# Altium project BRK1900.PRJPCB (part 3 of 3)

## Sheet DisplayPort-Sink-SATA.SchDoc: BRK1900 - DisplayPort Sink, SATA
size C; Organization: Opal Kelly; Address1: 13500 SW 72nd Ave STE 100; Address3: Portland, OR  97223; Address4: http://www.opalkelly.com; DocumentNumber: xxx; Revision: 1; SheetNumber: 6; SheetTotal: 9; PageSetup: Record=PageOptions¦CenterHorizontal=True¦CenterVertical=True¦PrintScale=0.52¦XCorrection=1.00¦YCorrection=1.00¦PrintKind=0¦BorderSize=5000000¦LeftOffset=0¦BottomOffset=0¦Orientation=2¦PaperLength=1000¦PaperWidth=1000¦Scale=100¦PaperSource=7¦PrintQuality=-4¦MediaType=1¦DitherType=10¦PaperKind=Letter¦PrintScaleMode=1
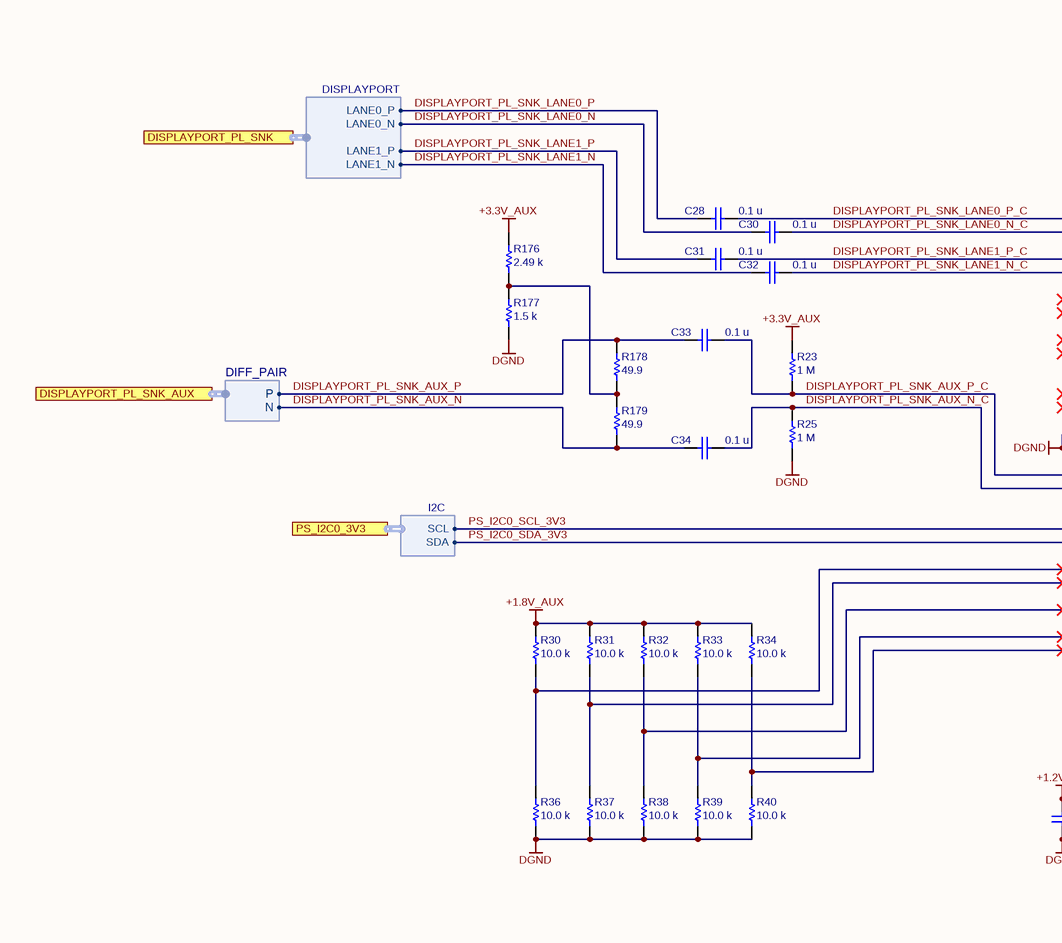
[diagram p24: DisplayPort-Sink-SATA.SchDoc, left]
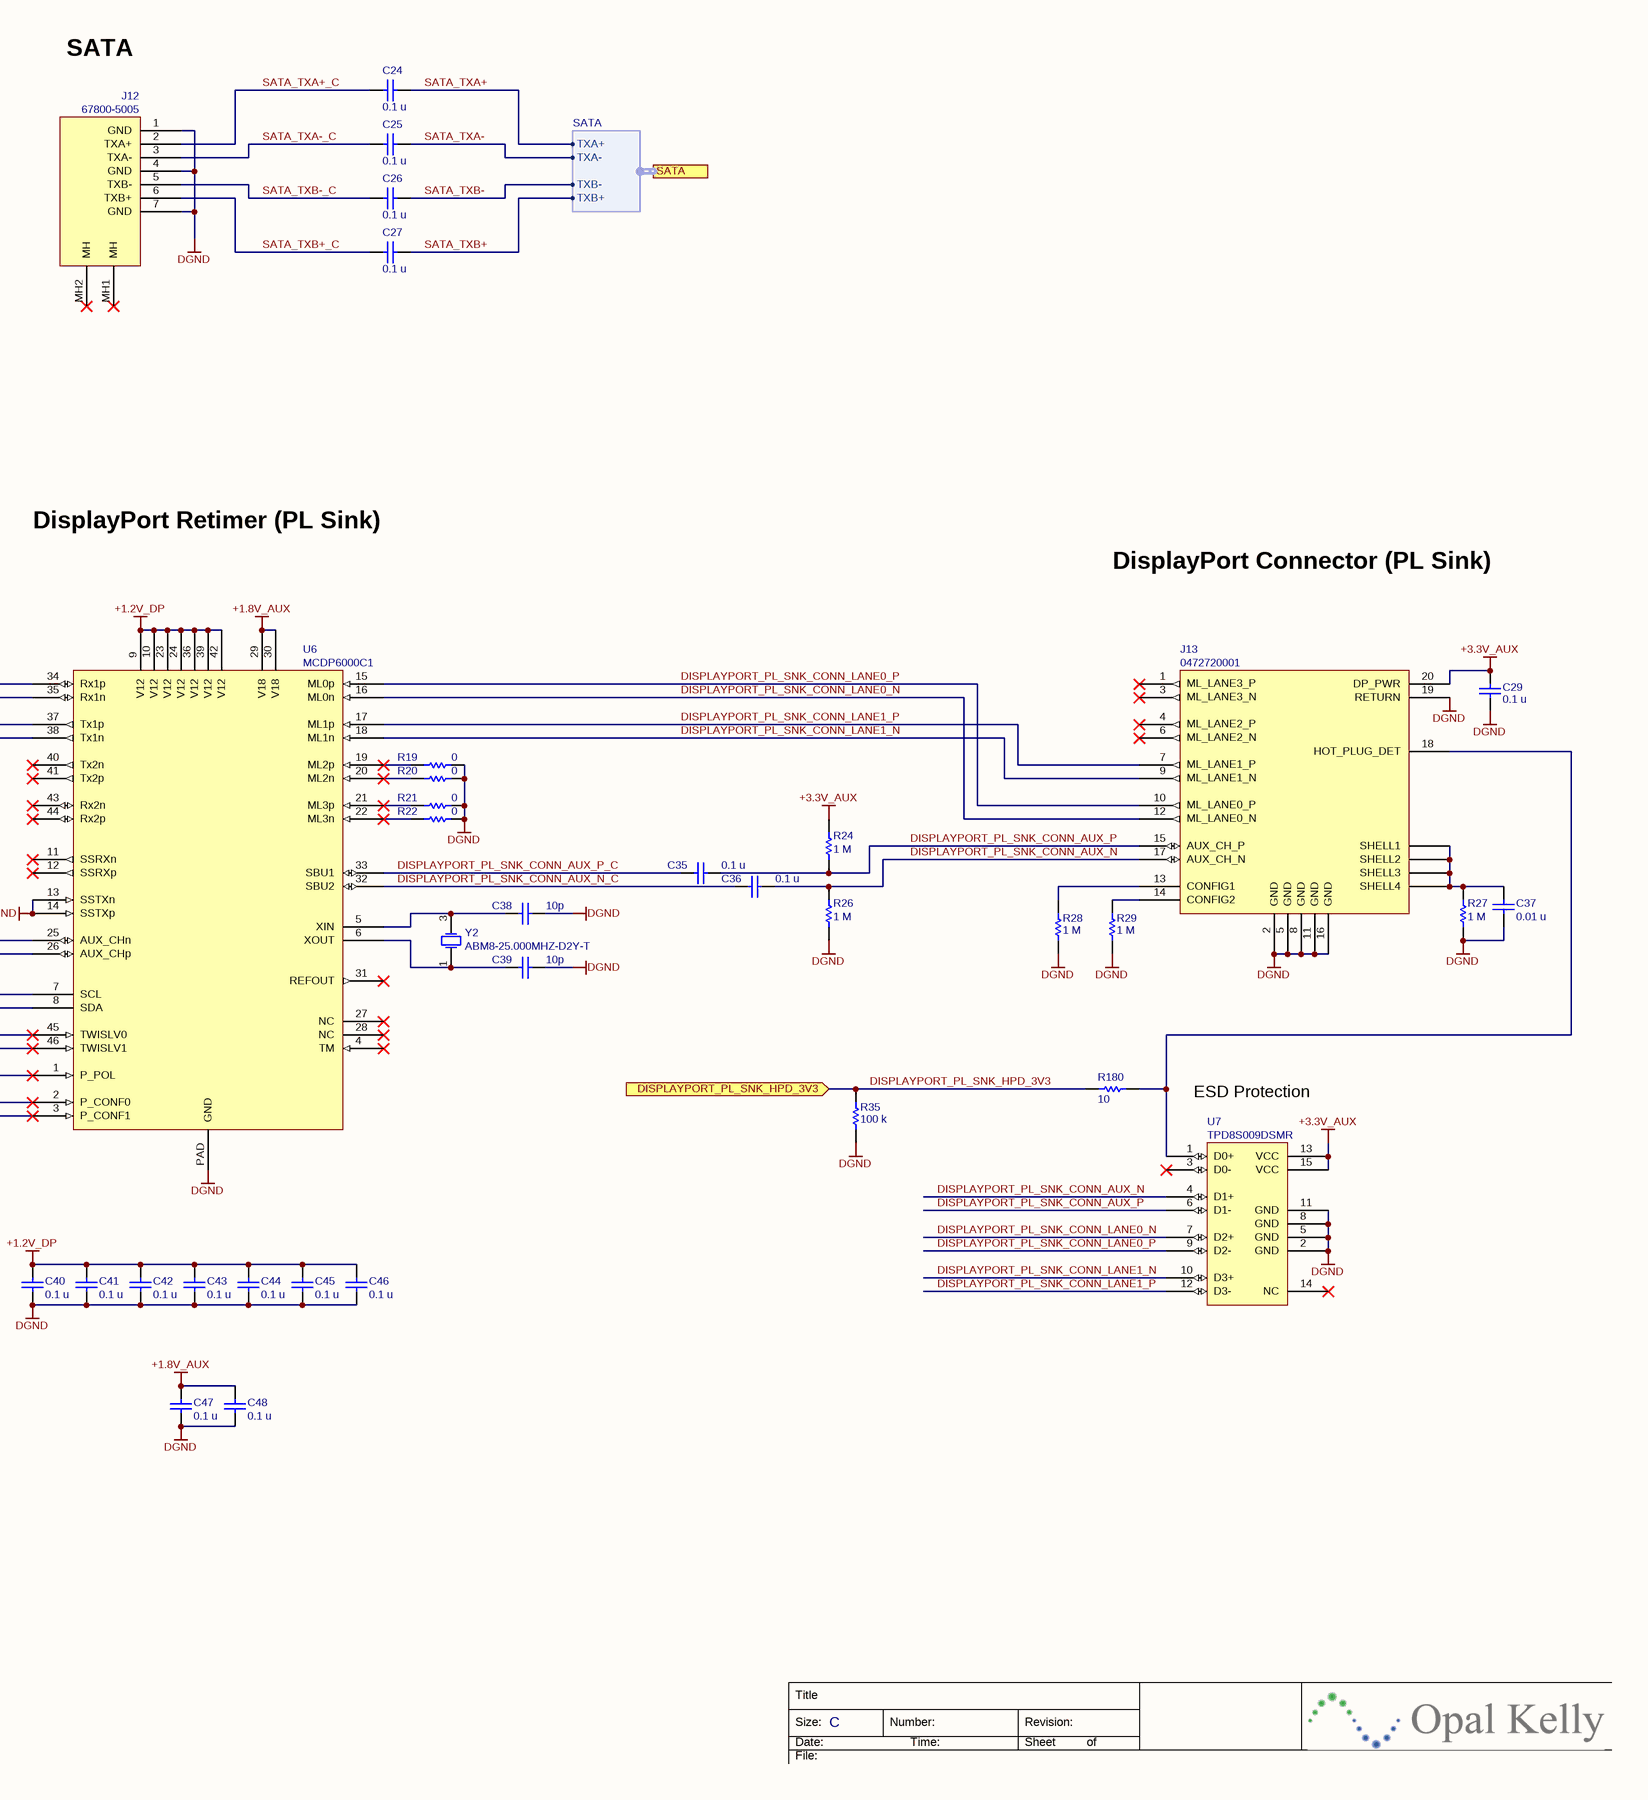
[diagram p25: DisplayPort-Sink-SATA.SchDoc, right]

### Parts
C24  value 0.1 u  [CAPC1005X06A]  (hidden comment: SM-0402, 10%, 10v)
C25  value 0.1 u  [CAPC1005X06A]  (hidden comment: SM-0402, 10%, 10v)
C26  value 0.1 u  [CAPC1005X06A]  (hidden comment: SM-0402, 10%, 10v)
C27  value 0.1 u  [CAPC1005X06A]  (hidden comment: SM-0402, 10%, 10v)
C28  value 0.1 u  [CAPC1005X06A]  (hidden comment: SM-0402, 10%, 10v)
C29  value 0.1 u  [CAPC1005X06A]  (hidden comment: SM-0402, 10%, 10v)
C30  value 0.1 u  [CAPC1005X06A]  (hidden comment: SM-0402, 10%, 10v)
C31  value 0.1 u  [CAPC1005X06A]  (hidden comment: SM-0402, 10%, 10v)
C32  value 0.1 u  [CAPC1005X06A]  (hidden comment: SM-0402, 10%, 10v)
C33  value 0.1 u  [CAPC1005X06A]  (hidden comment: SM-0402, 10%, 10v)
C34  value 0.1 u  [CAPC1005X06A]  (hidden comment: SM-0402, 10%, 10v)
C35  value 0.1 u  [CAPC1005X06A]  (hidden comment: SM-0402, 10%, 10v)
C36  value 0.1 u  [CAPC1005X06A]  (hidden comment: SM-0402, 10%, 10v)
C37  value 0.01 u  [CAPC1005X06A]  (hidden comment: C0402C103K4RACTU)
C38  value 10p  [CAPC1005X06A]  (hidden comment: CBR04C100J5GAC)
C39  value 10p  [CAPC1005X06A]  (hidden comment: CBR04C100J5GAC)
C40  value 0.1 u  [CAPC1005X06A]  (hidden comment: C0402C104K8PACTU)
C41  value 0.1 u  [CAPC1005X06A]  (hidden comment: C0402C104K8PACTU)
C42  value 0.1 u  [CAPC1005X06A]  (hidden comment: C0402C104K8PACTU)
C43  value 0.1 u  [CAPC1005X06A]  (hidden comment: C0402C104K8PACTU)
C44  value 0.1 u  [CAPC1005X06A]  (hidden comment: C0402C104K8PACTU)
C45  value 0.1 u  [CAPC1005X06A]  (hidden comment: C0402C104K8PACTU)
C46  value 0.1 u  [CAPC1005X06A]  (hidden comment: C0402C104K8PACTU)
C47  value 0.1 u  [CAPC1005X06A]  (hidden comment: C0402C104K8PACTU)
C48  value 0.1 u  [CAPC1005X06A]  (hidden comment: C0402C104K8PACTU)
J12  67800-5005  [MOLEX-67800-5005]
J13  0472720001  [0472720001]
R19  value 0  [RESC1005X06A]  (hidden comment: CRCW04020000Z0ED)
R20  value 0  [RESC1005X06A]  (hidden comment: CRCW04020000Z0ED)
R21  value 0  [RESC1005X06A]  (hidden comment: CRCW04020000Z0ED)
R22  value 0  [RESC1005X06A]  (hidden comment: CRCW04020000Z0ED)
R23  value 1 M  [RESC1005X06A]  (hidden comment: CRCW04021M00FKEDC)
R24  value 1 M  [RESC1005X06A]  (hidden comment: CRCW04021M00FKEDC)
R25  value 1 M  [RESC1005X06A]  (hidden comment: CRCW04021M00FKEDC)
R26  value 1 M  [RESC1005X06A]  (hidden comment: CRCW04021M00FKEDC)
R27  value 1 M  [RESC1005X06A]  (hidden comment: CRCW04021M00FKEDC)
R28  value 1 M  [RESC1005X06A]  (hidden comment: CRCW04021M00FKEDC)
R29  value 1 M  [RESC1005X06A]  (hidden comment: CRCW04021M00FKEDC)
R30  value 10.0 k  [RESC1005X06A]  (hidden comment: CRCW040210K0FKED)
R31  value 10.0 k  [RESC1005X06A]  (hidden comment: CRCW040210K0FKED)
R32  value 10.0 k  [RESC1005X06A]  (hidden comment: CRCW040210K0FKED)
R33  value 10.0 k  [RESC1005X06A]  (hidden comment: CRCW040210K0FKED)
R34  value 10.0 k  [RESC1005X06A]  (hidden comment: CRCW040210K0FKED)
R35  value 100 k  [RESC1005X06A]  (hidden comment: CRCW0402100KFKED)
R36  value 10.0 k  [RESC1005X06A]  (hidden comment: CRCW040210K0FKED)
R37  value 10.0 k  [RESC1005X06A]  (hidden comment: CRCW040210K0FKED)
R38  value 10.0 k  [RESC1005X06A]  (hidden comment: CRCW040210K0FKED)
R39  value 10.0 k  [RESC1005X06A]  (hidden comment: CRCW040210K0FKED)
R40  value 10.0 k  [RESC1005X06A]  (hidden comment: CRCW040210K0FKED)
R176  value 2.49 k  [RESC1005X06A]  (hidden comment: CRCW04022K49FKED)
R177  value 1.5 k  [RESC1005X06A]  (hidden comment: CRCW04021K50FKED)
R178  value 49.9  [RESC1005X06A]  (hidden comment: CRCW040249R9FKEDC)
R179  value 49.9  [RESC1005X06A]  (hidden comment: CRCW040249R9FKEDC)
R180  value 10  [RESC1005X06A]  (hidden comment: CRCW040210R0FKED)
U6  MCDP6000C1  [MCDP6000]
U7  TPD8S009DSMR  [TPD8S009DSMR]
Y2  ABM8-25.000MHZ-D2Y-T  [OSC_SMD_32x25]

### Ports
DISPLAYPORT_PL_SNK (harness DISPLAYPORT), DISPLAYPORT_PL_SNK_AUX (harness DIFF_PAIR), DISPLAYPORT_PL_SNK_HPD_3V3 (in), PS_I2C0_3V3 (harness I2C), SATA (harness SATA)

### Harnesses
DISPLAYPORT: LANE0_P, LANE0_N, LANE1_P, LANE1_N
DIFF_PAIR: P, N
SATA: TXA+, TXA-, TXB-, TXB+
I2C: SCL, SDA

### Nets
+1.2V_DP: C40.2 C41.2 C42.2 C43.2 C44.2 C45.2 C46.2 U6.9(V12) U6.10(V12) U6.23(V12) U6.24(V12) U6.36(V12) U6.39(V12) U6.42(V12)
+1.8V_AUX: C47.2 C48.2 R30.2 R31.2 R32.2 R33.2 R34.2 U6.29(V18) U6.30(V18)
+3.3V_AUX: C29.2 J13.20(DP_PWR) R23.2 R24.2 R176.2 U7.13(VCC) U7.15(VCC)
DGND: C29.1 C37.1 C38.2 C39.2 C40.1 C41.1 C42.1 C43.1 C44.1 C45.1 C46.1 C47.1 C48.1 J12.1(GND) J12.4(GND) J12.7(GND) J13.2(GND) J13.5(GND) J13.8(GND) J13.11(GND) J13.16(GND) J13.19(RETURN) R19.2 R20.2 R21.2 R22.2 R25.1 R26.1 R27.1 R28.1 R29.1 R35.1 R36.1 R37.1 R38.1 R39.1 R40.1 R177.1 U6.13(SSTXn) U6.14(SSTXp) U6.PAD(GND) U7.2(GND) U7.5(GND) U7.8(GND) U7.11(GND)
DISPLAYPORT_PL_SNK_AUX_N: C34.2 R179.1 ; port DISPLAYPORT_PL_SNK_AUX.N
DISPLAYPORT_PL_SNK_AUX_N_C: C34.1 R25.2 U6.26(AUX_CHp)
DISPLAYPORT_PL_SNK_AUX_P: C33.2 R178.2 ; port DISPLAYPORT_PL_SNK_AUX.P
DISPLAYPORT_PL_SNK_AUX_P_C: C33.1 R23.1 U6.25(AUX_CHn)
DISPLAYPORT_PL_SNK_CONN_AUX_N: C36.1 J13.17(AUX_CH_N) R26.2 U7.4(D1+)
DISPLAYPORT_PL_SNK_CONN_AUX_N_C: C36.2 U6.32(SBU2)
DISPLAYPORT_PL_SNK_CONN_AUX_P: C35.1 J13.15(AUX_CH_P) R24.1 U7.6(D1-)
DISPLAYPORT_PL_SNK_CONN_AUX_P_C: C35.2 U6.33(SBU1)
DISPLAYPORT_PL_SNK_CONN_LANE0_N: J13.12(ML_LANE3_N) U6.16(ML0n) U7.7(D2+)
DISPLAYPORT_PL_SNK_CONN_LANE0_P: J13.10(ML_LANE3_P) U6.15(ML0p) U7.9(D2-)
DISPLAYPORT_PL_SNK_CONN_LANE1_N: J13.9(ML_LANE2_N) U6.18(ML1n) U7.10(D3+)
DISPLAYPORT_PL_SNK_CONN_LANE1_P: J13.7(ML_LANE2_P) U6.17(ML1p) U7.12(D3-)
DISPLAYPORT_PL_SNK_HPD_3V3: R35.2 R180.1 ; port DISPLAYPORT_PL_SNK_HPD_3V3
DISPLAYPORT_PL_SNK_LANE0_N: C30.2 ; port DISPLAYPORT_PL_SNK.LANE0_N
DISPLAYPORT_PL_SNK_LANE0_N_C: C30.1 U6.35(Rx1n)
DISPLAYPORT_PL_SNK_LANE0_P: C28.2 ; port DISPLAYPORT_PL_SNK.LANE0_P
DISPLAYPORT_PL_SNK_LANE0_P_C: C28.1 U6.34(Rx1p)
DISPLAYPORT_PL_SNK_LANE1_N: C32.2 ; port DISPLAYPORT_PL_SNK.LANE1_N
DISPLAYPORT_PL_SNK_LANE1_N_C: C32.1 U6.38(Tx1n)
DISPLAYPORT_PL_SNK_LANE1_P: C31.2 ; port DISPLAYPORT_PL_SNK.LANE1_P
DISPLAYPORT_PL_SNK_LANE1_P_C: C31.1 U6.37(Tx1p)
PS_I2C0_SCL_3V3: U6.7(SCL) ; port PS_I2C0_3V3.SCL
PS_I2C0_SDA_3V3: U6.8(SDA) ; port PS_I2C0_3V3.SDA
SATA_TXA+: C24.2 ; port SATA.TXA+
SATA_TXA+_C: C24.1 J12.2(TXA+)
SATA_TXA-: C25.2 ; port SATA.TXA-
SATA_TXA-_C: C25.1 J12.3(TXA-)
SATA_TXB+: C27.2 ; port SATA.TXB+
SATA_TXB+_C: C27.1 J12.6(TXB+)
SATA_TXB-: C26.2 ; port SATA.TXB-
SATA_TXB-_C: C26.1 J12.5(TXB-)
NetC37_2: C37.2 J13.SHELL1 J13.SHELL2 J13.SHELL3 J13.SHELL4 R27.2
NetC38_1: C38.1 U6.5(XIN) Y2.3(OSC2)
NetC39_1: C39.1 U6.6(XOUT) Y2.1(OSC1)
NetJ13_13: J13.13(CONFIG1) R28.2
NetJ13_14: J13.14(CONFIG2) R29.2
NetJ13_18: J13.18(HOT_PLUG_DET) R180.2 U7.1(D0+)
NetR19_1: R19.1 U6.19(ML2p)
NetR20_1: R20.1 U6.20(ML2n)
NetR21_1: R21.1 U6.21(ML3p)
NetR22_1: R22.1 U6.22(ML3n)
NetR30_1: R30.1 R36.2 U6.45(TWISLV0)
NetR31_1: R31.1 R37.2 U6.46(TWISLV1)
NetR32_1: R32.1 R38.2 U6.1(P_POL)
NetR33_1: R33.1 R39.2 U6.2(P_CONF0)
NetR34_1: R34.1 R40.2 U6.3(P_CONF1)
NetR176_1: R176.1 R177.2 R178.1 R179.2

Not connected (* = marked no-connect by the designer): J12 MH1(MH)* MH2(MH)*; J13 1(ML_LANE0_P)* 3(ML_LANE0_N)* 4(ML_LANE1_P)* 6(ML_LANE1_N)*; U6 4(TM)* 11(SSRXn)* 12(SSRXp)* 27(NC)* 28(NC)* 31(REFOUT)* 40(Tx2n)* 41(Tx2p)* 43(Rx2n)* 44(Rx2p)*; U7 3(D0-)* 14(NC)*

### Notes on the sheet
- SATA
- DisplayPort Retimer (PL Sink)
- DisplayPort Connector (PL Sink)
- ESD Protection
- Title
- Size:
- Date:
- File:
- C
- Number:
- Time:
- Revision:
- Sheet
- of

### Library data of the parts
C24-C36 = 000070: Partnumber: 000070; manufacturer: Kemet; manufacturer_pn: C0402C104K8PACTU; ValueFloat: 1E-7; id: 750; inventory_price: 0.0023; reorder_quantity: 70000; x_tolerance: 10
C37 = 000295: Partnumber: 000295; manufacturer: Kemet; ValueFloat: 1E-8; x_tolerance: 10
C38 C39 = 001297: Partnumber: 001297; manufacturer: Kemet; ValueFloat: 1E-11; x_tolerance: 5; x_voltage-rating: 50
C40-C48 = 000070: Partnumber: 000070; manufacturer: Kemet; ValueFloat: 1E-7; x_tolerance: 10
J12 = 000988: SATA 7-pin receptacle; Manufacturer: Molex; partnumber: 000988; Description 2: Vertical Mount, SMD, Latch, 15u Gold; x_lifecycle_status: Production
J13 = 001943: Partnumber: 001943; manufacturer: Molex
R19-R22 = 000755: Thick-film resistor; Manufacturer: Vishay; partnumber: 000755; x_tolerance: 1
R23-R29 = 001850: Partnumber: 001850; manufacturer: Vishay; ValueFloat: 1000000; x_tolerance: 5
R30-R34 R36-R40 = 001521: Partnumber: 001521; manufacturer: Vishay; ValueFloat: 10000; x_tolerance: 1
R35 = 001070: Partnumber: 001070; manufacturer: Vishay; ValueFloat: 100000; x_tolerance: 1
R176 = 001388: Partnumber: 001388; manufacturer: Vishay; ValueFloat: 2490; x_tolerance: 1
R177 = 002012: Partnumber: 002012; manufacturer: Vishay; ValueFloat: 1500; x_tolerance: 1
R178 R179 = 001715: Partnumber: 001715; manufacturer: Vishay; x_tolerance: 1
R180 = 000969: Partnumber: 000969; manufacturer: Vishay; x_tolerance: 1
U6 = 002001: Partnumber: 002001; manufacturer: Kinetic Technologies
U7 = 001946: Partnumber: 001946; manufacturer: Texas Instruments
Y2 = 001531: Partnumber: 001531; manufacturer: Abracon

## Sheet DisplayPort-Source.SchDoc: BRK1900 - DisplayPort Source
size C; Organization: Opal Kelly; Address1: 13500 SW 72nd Ave STE 100; Address3: Portland, OR  97223; Address4: http://www.opalkelly.com; DocumentNumber: xxx; Revision: 1; SheetNumber: 5; SheetTotal: 9; PageSetup: Record=PageOptions¦CenterHorizontal=True¦CenterVertical=True¦PrintScale=0.52¦XCorrection=1.00¦YCorrection=1.00¦PrintKind=0¦BorderSize=5000000¦LeftOffset=0¦BottomOffset=0¦Orientation=2¦PaperLength=1000¦PaperWidth=1000¦Scale=100¦PaperSource=7¦PrintQuality=-4¦MediaType=1¦DitherType=10¦PaperKind=Letter¦PrintScaleMode=1
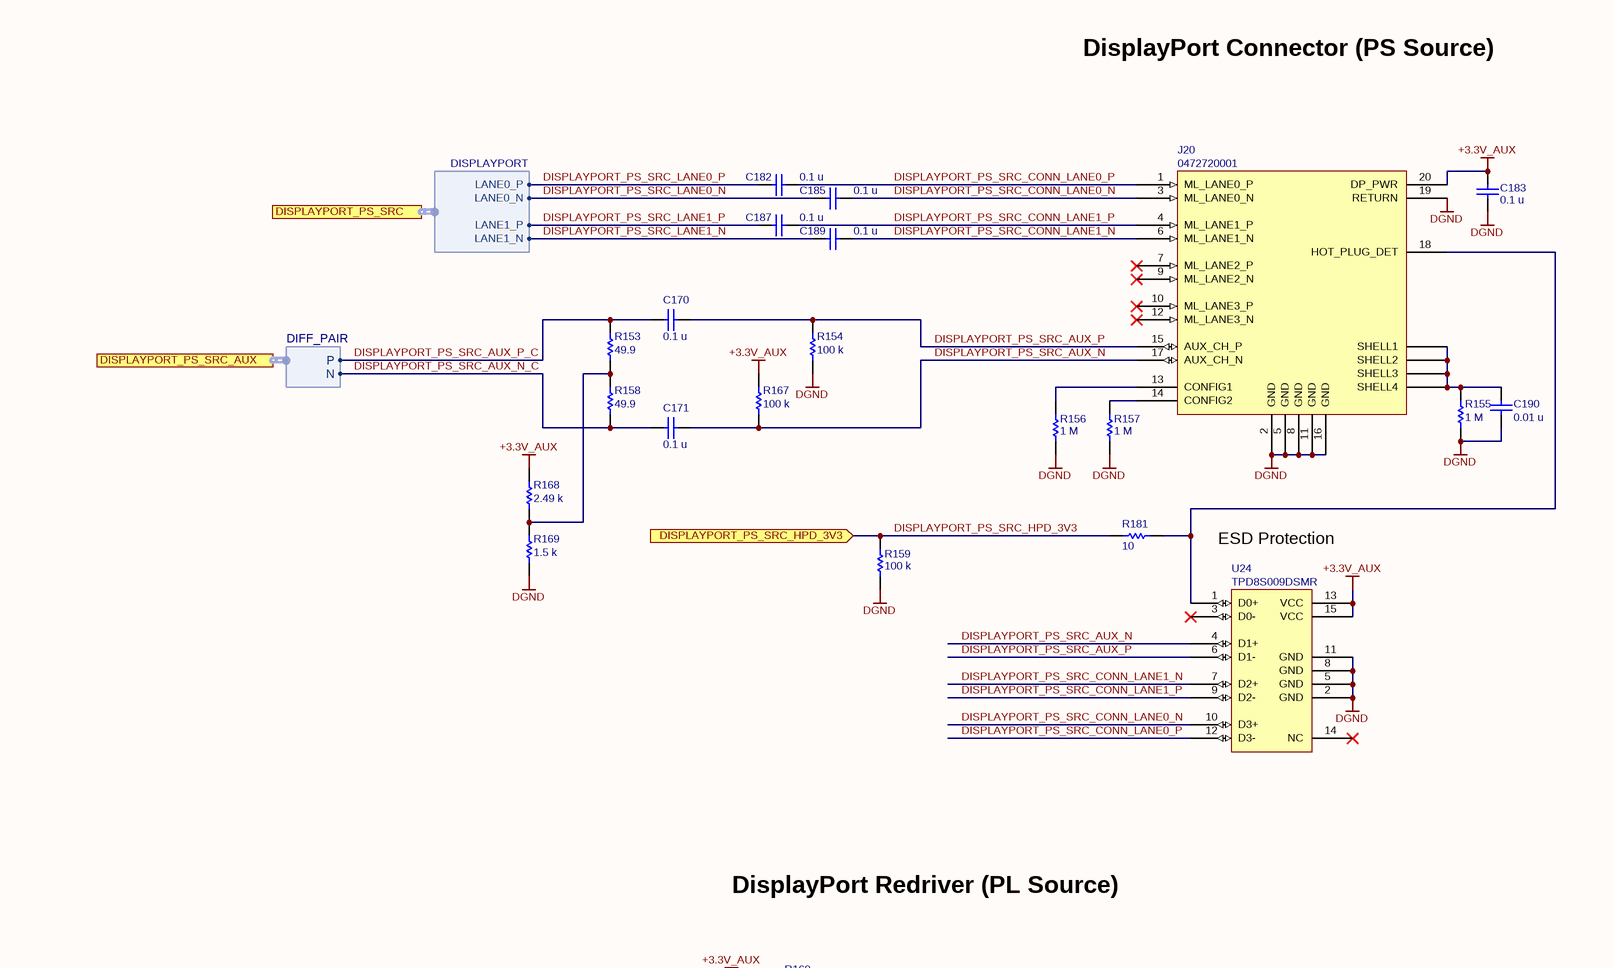
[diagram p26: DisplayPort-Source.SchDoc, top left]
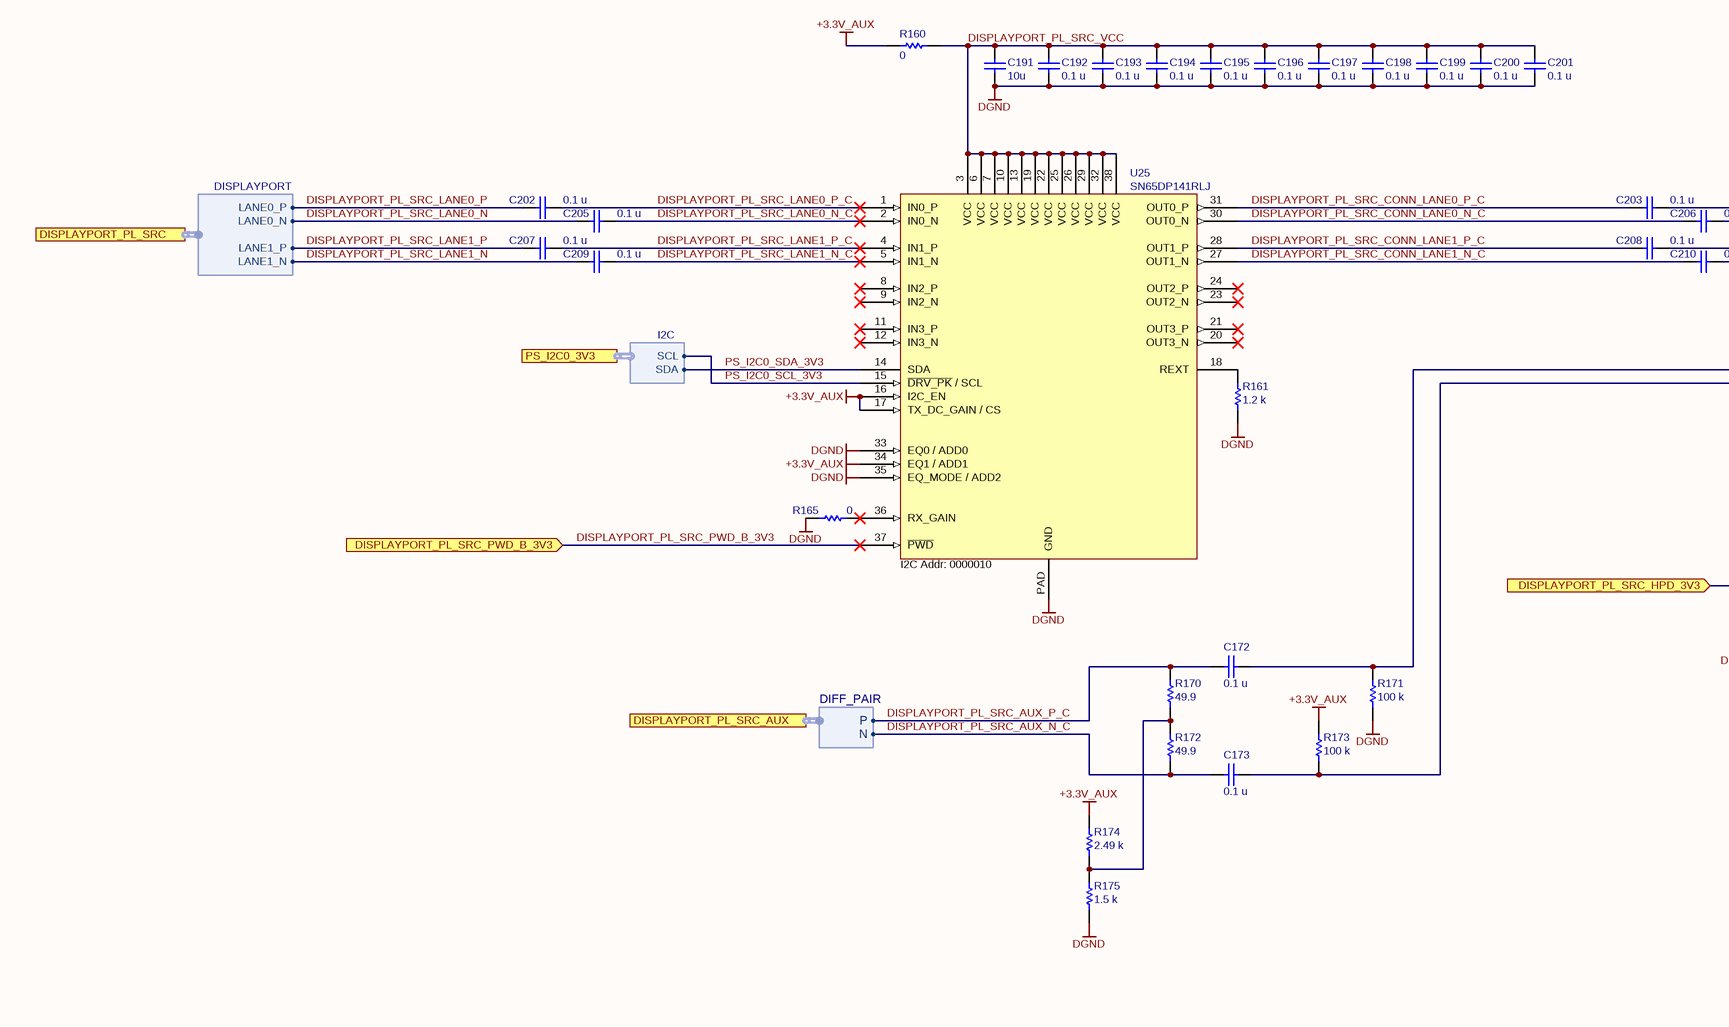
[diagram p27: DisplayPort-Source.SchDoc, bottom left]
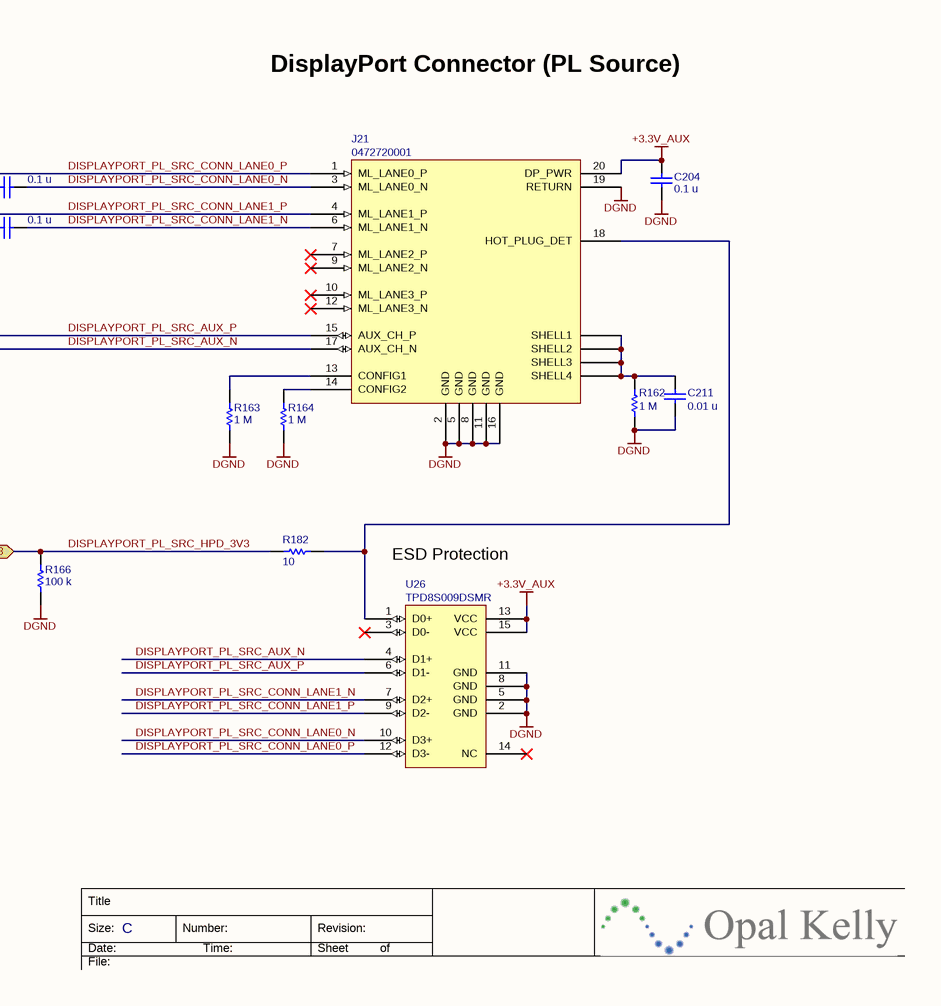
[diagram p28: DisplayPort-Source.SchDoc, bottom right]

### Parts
C170  value 0.1 u  [CAPC1005X06A]  (hidden comment: SM-0402, 10%, 10v)
C171  value 0.1 u  [CAPC1005X06A]  (hidden comment: SM-0402, 10%, 10v)
C172  value 0.1 u  [CAPC1005X06A]  (hidden comment: SM-0402, 10%, 10v)
C173  value 0.1 u  [CAPC1005X06A]  (hidden comment: SM-0402, 10%, 10v)
C182  value 0.1 u  [CAPC1005X06A]  (hidden comment: SM-0402, 10%, 10v)
C183  value 0.1 u  [CAPC1005X06A]  (hidden comment: SM-0402, 10%, 10v)
C185  value 0.1 u  [CAPC1005X06A]  (hidden comment: SM-0402, 10%, 10v)
C187  value 0.1 u  [CAPC1005X06A]  (hidden comment: SM-0402, 10%, 10v)
C189  value 0.1 u  [CAPC1005X06A]  (hidden comment: SM-0402, 10%, 10v)
C190  value 0.01 u  [CAPC1005X06A]  (hidden comment: C0402C103K4RACTU)
C191  value 10u  [CAPC1608X09N]  (hidden comment: LMK107BJ106MALTD)
C192  value 0.1 u  [CAPC1005X06A]  (hidden comment: C0402C104K8PACTU)
C193  value 0.1 u  [CAPC1005X06A]  (hidden comment: C0402C104K8PACTU)
C194  value 0.1 u  [CAPC1005X06A]  (hidden comment: C0402C104K8PACTU)
C195  value 0.1 u  [CAPC1005X06A]  (hidden comment: C0402C104K8PACTU)
C196  value 0.1 u  [CAPC1005X06A]  (hidden comment: C0402C104K8PACTU)
C197  value 0.1 u  [CAPC1005X06A]  (hidden comment: C0402C104K8PACTU)
C198  value 0.1 u  [CAPC1005X06A]  (hidden comment: C0402C104K8PACTU)
C199  value 0.1 u  [CAPC1005X06A]  (hidden comment: C0402C104K8PACTU)
C200  value 0.1 u  [CAPC1005X06A]  (hidden comment: C0402C104K8PACTU)
C201  value 0.1 u  [CAPC1005X06A]  (hidden comment: C0402C104K8PACTU)
C202  value 0.1 u  [CAPC1005X06A]  (hidden comment: SM-0402, 10%, 10v)
C203  value 0.1 u  [CAPC1005X06A]  (hidden comment: SM-0402, 10%, 10v)
C204  value 0.1 u  [CAPC1005X06A]  (hidden comment: SM-0402, 10%, 10v)
C205  value 0.1 u  [CAPC1005X06A]  (hidden comment: SM-0402, 10%, 10v)
C206  value 0.1 u  [CAPC1005X06A]  (hidden comment: SM-0402, 10%, 10v)
C207  value 0.1 u  [CAPC1005X06A]  (hidden comment: SM-0402, 10%, 10v)
C208  value 0.1 u  [CAPC1005X06A]  (hidden comment: SM-0402, 10%, 10v)
C209  value 0.1 u  [CAPC1005X06A]  (hidden comment: SM-0402, 10%, 10v)
C210  value 0.1 u  [CAPC1005X06A]  (hidden comment: SM-0402, 10%, 10v)
C211  value 0.01 u  [CAPC1005X06A]  (hidden comment: C0402C103K4RACTU)
J20  0472720001  [0472720001]
J21  0472720001  [0472720001]
R153  value 49.9  [RESC1005X06A]  (hidden comment: CRCW040249R9FKEDC)
R154  value 100 k  [RESC1005X06A]  (hidden comment: CRCW0402100KFKED)
R155  value 1 M  [RESC1005X06A]  (hidden comment: CRCW04021M00FKEDC)
R156  value 1 M  [RESC1005X06A]  (hidden comment: CRCW04021M00FKEDC)
R157  value 1 M  [RESC1005X06A]  (hidden comment: CRCW04021M00FKEDC)
R158  value 49.9  [RESC1005X06A]  (hidden comment: CRCW040249R9FKEDC)
R159  value 100 k  [RESC1005X06A]  (hidden comment: CRCW0402100KFKED)
R160  value 0  [RESC1608N]  (hidden comment: CRCW06030000Z0EA)
R161  value 1.2 k  [RESC1005X06A]  (hidden comment: CRCW04021K20FKEDC)
R162  value 1 M  [RESC1005X06A]  (hidden comment: CRCW04021M00FKEDC)
R163  value 1 M  [RESC1005X06A]  (hidden comment: CRCW04021M00FKEDC)
R164  value 1 M  [RESC1005X06A]  (hidden comment: CRCW04021M00FKEDC)
R165  value 0  [RESC1005X06A]  (hidden comment: CRCW04020000Z0ED)
R166  value 100 k  [RESC1005X06A]  (hidden comment: CRCW0402100KFKED)
R167  value 100 k  [RESC1005X06A]  (hidden comment: CRCW0402100KFKED)
R168  value 2.49 k  [RESC1005X06A]  (hidden comment: CRCW04022K49FKED)
R169  value 1.5 k  [RESC1005X06A]  (hidden comment: CRCW04021K50FKED)
R170  value 49.9  [RESC1005X06A]  (hidden comment: CRCW040249R9FKEDC)
R171  value 100 k  [RESC1005X06A]  (hidden comment: CRCW0402100KFKED)
R172  value 49.9  [RESC1005X06A]  (hidden comment: CRCW040249R9FKEDC)
R173  value 100 k  [RESC1005X06A]  (hidden comment: CRCW0402100KFKED)
R174  value 2.49 k  [RESC1005X06A]  (hidden comment: CRCW04022K49FKED)
R175  value 1.5 k  [RESC1005X06A]  (hidden comment: CRCW04021K50FKED)
R181  value 10  [RESC1005X06A]  (hidden comment: CRCW040210R0FKED)
R182  value 10  [RESC1005X06A]  (hidden comment: CRCW040210R0FKED)
U24  TPD8S009DSMR  [TPD8S009DSMR]
U25  SN65DP141RLJ  [SN65DP141]
U26  TPD8S009DSMR  [TPD8S009DSMR]

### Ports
DISPLAYPORT_PL_SRC (harness DISPLAYPORT), DISPLAYPORT_PL_SRC_AUX (harness DIFF_PAIR), DISPLAYPORT_PL_SRC_HPD_3V3 (in), DISPLAYPORT_PL_SRC_PWD_B_3V3 (in), DISPLAYPORT_PS_SRC (harness DISPLAYPORT), DISPLAYPORT_PS_SRC_AUX (harness DIFF_PAIR), DISPLAYPORT_PS_SRC_HPD_3V3 (in), PS_I2C0_3V3 (harness I2C)

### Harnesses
DISPLAYPORT: LANE0_P, LANE0_N, LANE1_P, LANE1_N
DIFF_PAIR: P, N
I2C: SCL, SDA

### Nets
+3.3V_AUX: C183.2 C204.2 J20.20(DP_PWR) J21.20(DP_PWR) R160.1 R167.2 R168.2 R173.2 R174.2 U24.13(VCC) U24.15(VCC) U25.16(I2C_EN) U25.17(TX_DC_GAIN_/_CS) U25.34(EQ1_/_ADD1) U26.13(VCC) U26.15(VCC)
DGND: C183.1 C190.1 C191.1 C192.1 C193.1 C194.1 C195.1 C196.1 C197.1 C198.1 C199.1 C200.1 C201.1 C204.1 C211.1 J20.2(GND) J20.5(GND) J20.8(GND) J20.11(GND) J20.16(GND) J20.19(RETURN) J21.2(GND) J21.5(GND) J21.8(GND) J21.11(GND) J21.16(GND) J21.19(RETURN) R154.1 R155.1 R156.1 R157.1 R159.1 R161.1 R162.1 R163.1 R164.1 R165.1 R166.1 R169.1 R171.1 R175.1 U24.2(GND) U24.5(GND) U24.8(GND) U24.11(GND) U25.33(EQ0_/_ADD0) U25.35(EQ_MODE_/_ADD2) U25.PAD(GND) U26.2(GND) U26.5(GND) U26.8(GND) U26.11(GND)
DISPLAYPORT_PL_SRC_AUX_N: C173.1 J21.17(AUX_CH_N) R173.1 U26.4(D1+)
DISPLAYPORT_PL_SRC_AUX_N_C: C173.2 R172.1 ; port DISPLAYPORT_PL_SRC_AUX.N
DISPLAYPORT_PL_SRC_AUX_P: C172.1 J21.15(AUX_CH_P) R171.2 U26.6(D1-)
DISPLAYPORT_PL_SRC_AUX_P_C: C172.2 R170.2 ; port DISPLAYPORT_PL_SRC_AUX.P
DISPLAYPORT_PL_SRC_CONN_LANE0_N: C206.1 J21.3(ML_LANE0_N) U26.10(D3+)
DISPLAYPORT_PL_SRC_CONN_LANE0_N_C: C206.2 U25.30(OUT0_N)
DISPLAYPORT_PL_SRC_CONN_LANE0_P: C203.1 J21.1(ML_LANE0_P) U26.12(D3-)
DISPLAYPORT_PL_SRC_CONN_LANE0_P_C: C203.2 U25.31(OUT0_P)
DISPLAYPORT_PL_SRC_CONN_LANE1_N: C210.1 J21.6(ML_LANE1_N) U26.7(D2+)
DISPLAYPORT_PL_SRC_CONN_LANE1_N_C: C210.2 U25.27(OUT1_N)
DISPLAYPORT_PL_SRC_CONN_LANE1_P: C208.1 J21.4(ML_LANE1_P) U26.9(D2-)
DISPLAYPORT_PL_SRC_CONN_LANE1_P_C: C208.2 U25.28(OUT1_P)
DISPLAYPORT_PL_SRC_HPD_3V3: R166.2 R182.1 ; port DISPLAYPORT_PL_SRC_HPD_3V3
DISPLAYPORT_PL_SRC_LANE0_N: C205.2 ; port DISPLAYPORT_PL_SRC.LANE0_N
DISPLAYPORT_PL_SRC_LANE0_N_C: C205.1 U25.2(IN0_N)
DISPLAYPORT_PL_SRC_LANE0_P: C202.2 ; port DISPLAYPORT_PL_SRC.LANE0_P
DISPLAYPORT_PL_SRC_LANE0_P_C: C202.1 U25.1(IN0_P)
DISPLAYPORT_PL_SRC_LANE1_N: C209.2 ; port DISPLAYPORT_PL_SRC.LANE1_N
DISPLAYPORT_PL_SRC_LANE1_N_C: C209.1 U25.5(IN1_N)
DISPLAYPORT_PL_SRC_LANE1_P: C207.2 ; port DISPLAYPORT_PL_SRC.LANE1_P
DISPLAYPORT_PL_SRC_LANE1_P_C: C207.1 U25.4(IN1_P)
DISPLAYPORT_PL_SRC_PWD_B_3V3: U25.37(~{PWD}) ; port DISPLAYPORT_PL_SRC_PWD_B_3V3
DISPLAYPORT_PL_SRC_VCC: C191.2 C192.2 C193.2 C194.2 C195.2 C196.2 C197.2 C198.2 C199.2 C200.2 C201.2 R160.2 U25.3(VCC) U25.6(VCC) U25.7(VCC) U25.10(VCC) U25.13(VCC) U25.19(VCC) U25.22(VCC) U25.25(VCC) U25.26(VCC) U25.29(VCC) U25.32(VCC) U25.38(VCC)
DISPLAYPORT_PS_SRC_AUX_N: C171.1 J20.17(AUX_CH_N) R167.1 U24.4(D1+)
DISPLAYPORT_PS_SRC_AUX_N_C: C171.2 R158.1 ; port DISPLAYPORT_PS_SRC_AUX.N
DISPLAYPORT_PS_SRC_AUX_P: C170.1 J20.15(AUX_CH_P) R154.2 U24.6(D1-)
DISPLAYPORT_PS_SRC_AUX_P_C: C170.2 R153.2 ; port DISPLAYPORT_PS_SRC_AUX.P
DISPLAYPORT_PS_SRC_CONN_LANE0_N: C185.1 J20.3(ML_LANE0_N) U24.10(D3+)
DISPLAYPORT_PS_SRC_CONN_LANE0_P: C182.1 J20.1(ML_LANE0_P) U24.12(D3-)
DISPLAYPORT_PS_SRC_CONN_LANE1_N: C189.1 J20.6(ML_LANE1_N) U24.7(D2+)
DISPLAYPORT_PS_SRC_CONN_LANE1_P: C187.1 J20.4(ML_LANE1_P) U24.9(D2-)
DISPLAYPORT_PS_SRC_HPD_3V3: R159.2 R181.1 ; port DISPLAYPORT_PS_SRC_HPD_3V3
DISPLAYPORT_PS_SRC_LANE0_N: C185.2 ; port DISPLAYPORT_PS_SRC.LANE0_N
DISPLAYPORT_PS_SRC_LANE0_P: C182.2 ; port DISPLAYPORT_PS_SRC.LANE0_P
DISPLAYPORT_PS_SRC_LANE1_N: C189.2 ; port DISPLAYPORT_PS_SRC.LANE1_N
DISPLAYPORT_PS_SRC_LANE1_P: C187.2 ; port DISPLAYPORT_PS_SRC.LANE1_P
PS_I2C0_SCL_3V3: U25.15(~{DRV_PK}_/_SCL) ; port PS_I2C0_3V3.SCL
PS_I2C0_SDA_3V3: U25.14(SDA) ; port PS_I2C0_3V3.SDA
NetC190_2: C190.2 J20.SHELL1 J20.SHELL2 J20.SHELL3 J20.SHELL4 R155.2
NetC211_2: C211.2 J21.SHELL1 J21.SHELL2 J21.SHELL3 J21.SHELL4 R162.2
NetJ20_13: J20.13(CONFIG1) R156.2
NetJ20_14: J20.14(CONFIG2) R157.2
NetJ20_18: J20.18(HOT_PLUG_DET) R181.2 U24.1(D0+)
NetJ21_13: J21.13(CONFIG1) R163.2
NetJ21_14: J21.14(CONFIG2) R164.2
NetJ21_18: J21.18(HOT_PLUG_DET) R182.2 U26.1(D0+)
NetR153_1: R153.1 R158.2 R168.1 R169.2
NetR161_2: R161.2 U25.18(REXT)
NetR165_2: R165.2 U25.36(RX_GAIN)
NetR170_1: R170.1 R172.2 R174.1 R175.2

Not connected (* = marked no-connect by the designer): J20 7(ML_LANE2_P)* 9(ML_LANE2_N)* 10(ML_LANE3_P)* 12(ML_LANE3_N)*; J21 7(ML_LANE2_P)* 9(ML_LANE2_N)* 10(ML_LANE3_P)* 12(ML_LANE3_N)*; U24 3(D0-)* 14(NC)*; U25 8(IN2_P)* 9(IN2_N)* 11(IN3_P)* 12(IN3_N)* 20(OUT3_N)* 21(OUT3_P)* 23(OUT2_N)* 24(OUT2_P)*; U26 3(D0-)* 14(NC)*

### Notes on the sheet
- DisplayPort Connector (PS Source)
- ESD Protection
- DisplayPort Redriver (PL Source)
- DisplayPort Connector (PL Source)
- (near U25) I2C Addr: 0000010
- Title
- Size:
- Date:
- File:
- C
- Number:
- Time:
- Revision:
- Sheet
- of

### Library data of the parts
C170-C173 C182 C183 C185 C187 C189 C202-C210 = 000070: as C24-C36 on sheet DisplayPort-Sink-SATA
C190 C211 = 000295: as C37 on sheet DisplayPort-Sink-SATA
C191 = 001346: Partnumber: 001346; manufacturer: Taiyo Yuden; ValueFloat: 1E-5; x_tolerance: 20
C192-C201 = 000070: as C40-C48 on sheet DisplayPort-Sink-SATA
J20 J21 = 001943: Partnumber: 001943; manufacturer: Molex
R153 R158 R170 R172 = 001715: as R178 on sheet DisplayPort-Sink-SATA
R154 R159 R166 R167 R171 R173 = 001070: as R35 on sheet DisplayPort-Sink-SATA
R155-R157 R162-R164 = 001850: as R23 on sheet DisplayPort-Sink-SATA
R160 = 000411: Partnumber: 000411; manufacturer: Vishay
R161 = 002008: Partnumber: 002008; manufacturer: Vishay; ValueFloat: 1200; x_tolerance: 1
R165 = 000755: as R19-R22 on sheet DisplayPort-Sink-SATA
R168 R174 = 001388: as R176 on sheet DisplayPort-Sink-SATA
R169 R175 = 002012: as R177 on sheet DisplayPort-Sink-SATA
R181 R182 = 000969: as R180 on sheet DisplayPort-Sink-SATA
U24 U26 = 001946: as U7 on sheet DisplayPort-Sink-SATA
U25 = 002007: Partnumber: 002007; manufacturer: Texas Instruments

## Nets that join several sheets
+1.2V_DP: Power (7 pins), DisplayPort-Sink-SATA (14 pins)
+1.2V_ETH: USB_Ethernet (17 pins), Power (6 pins)
+1.8V: Top (TP1.1), Expansion-MC2 (MC2.1 MC2.3)
+1.8V_AUX: USB_Ethernet (30 pins), Expansion-MC1 (C1.2 J2.2 J4.18), Expansion-MC2 (J5.69 J5.70 J5.71), Power (6 pins), DisplayPort-Sink-SATA (9 pins)
+3.3V: Top (TP3.1), Expansion-MC3 (MC3.166 MC3.168)
+3.3V_AUX: USB_Ethernet (18 pins), Expansion-MC1 (6 pins), Expansion-MC2 (18 pins), Expansion-MC3 (9 pins), Power (24 pins), DisplayPort-Sink-SATA (7 pins), DisplayPort-Source (16 pins)
+3.3V_QSFP: QSFP (22 pins), Power (7 pins)
+5V_AUX: USB_Ethernet (7 pins), Power (7 pins)
+5V_SZG: Expansion-MC1 (J1.2), Expansion-MC2 (J6.2 J7.2), Expansion-MC3 (J8.2 J9.2 J11.2), Power (7 pins)
+VDCIN: Expansion-MC3 (12 pins), Power (17 pins)
DGND: Top (TP2.1 TP5.1 TP8.1 TP11.1), USB_Ethernet (90 pins), QSFP (50 pins), Expansion-MC1 (46 pins), Expansion-MC2 (41 pins), Expansion-MC3 (25 pins), Power (74 pins), DisplayPort-Sink-SATA (45 pins), DisplayPort-Source (52 pins)
VCCO_28: Top (TP6.1), Expansion-MC1 (J1.39), Expansion-MC2 (J7.39), Expansion-MC3 (MC3.158)
VCCO_67: Top (TP12.1), Expansion-MC2 (J6.39), Expansion-MC3 (C23.2 J11.39 MC3.103 U5.11)
VCCO_68: Top (TP7.1), Expansion-MC3 (C19.2 J9.39 MC3.51 U4.11)
VCCO_87_88: Top (TP13.1), QSFP (18 pins), Expansion-MC3 (J8.39 MC3.25)
VREF_28: Top (TP9.1), Expansion-MC3 (MC3.162)
VREF_67: Top (TP4.1), Expansion-MC3 (MC3.94)
VREF_68: Top (TP10.1), Expansion-MC3 (MC3.50)
DISPLAYPORT_PL_SNK_AUX_N: Expansion-MC3 (MC3.99), DisplayPort-Sink-SATA (C34.2 R179.1)
DISPLAYPORT_PL_SNK_AUX_P: Expansion-MC3 (MC3.97), DisplayPort-Sink-SATA (C33.2 R178.2)
DISPLAYPORT_PL_SNK_HPD_3V3: Expansion-MC3 (U4.2), DisplayPort-Sink-SATA (R35.2 R180.1)
DISPLAYPORT_PL_SNK_LANE0_N: Expansion-MC2 (MC2.107), DisplayPort-Sink-SATA (C30.2)
DISPLAYPORT_PL_SNK_LANE0_P: Expansion-MC2 (MC2.105), DisplayPort-Sink-SATA (C28.2)
DISPLAYPORT_PL_SNK_LANE1_N: Expansion-MC2 (MC2.111), DisplayPort-Sink-SATA (C32.2)
DISPLAYPORT_PL_SNK_LANE1_P: Expansion-MC2 (MC2.109), DisplayPort-Sink-SATA (C31.2)
DISPLAYPORT_PL_SRC_AUX_N_C: Expansion-MC3 (MC3.89), DisplayPort-Source (C173.2 R172.1)
DISPLAYPORT_PL_SRC_AUX_P_C: Expansion-MC3 (MC3.87), DisplayPort-Source (C172.2 R170.2)
DISPLAYPORT_PL_SRC_HPD_3V3: Expansion-MC3 (U4.3), DisplayPort-Source (R166.2 R182.1)
DISPLAYPORT_PL_SRC_LANE0_N: Expansion-MC2 (MC2.108), DisplayPort-Source (C205.2)
DISPLAYPORT_PL_SRC_LANE0_P: Expansion-MC2 (MC2.106), DisplayPort-Source (C202.2)
DISPLAYPORT_PL_SRC_LANE1_N: Expansion-MC2 (MC2.112), DisplayPort-Source (C209.2)
DISPLAYPORT_PL_SRC_LANE1_P: Expansion-MC2 (MC2.110), DisplayPort-Source (C207.2)
DISPLAYPORT_PL_SRC_PWD_B_3V3: Expansion-MC3 (U4.4), DisplayPort-Source (U25.37)
DISPLAYPORT_PS_SRC_AUX_N_C: Expansion-MC3 (MC3.153), DisplayPort-Source (C171.2 R158.1)
DISPLAYPORT_PS_SRC_AUX_P_C: Expansion-MC3 (MC3.151), DisplayPort-Source (C170.2 R153.2)
DISPLAYPORT_PS_SRC_HPD_3V3: Expansion-MC3 (U5.2), DisplayPort-Source (R159.2 R181.1)
DISPLAYPORT_PS_SRC_LANE0_N: Expansion-MC2 (MC2.28), DisplayPort-Source (C185.2)
DISPLAYPORT_PS_SRC_LANE0_P: Expansion-MC2 (MC2.26), DisplayPort-Source (C182.2)
DISPLAYPORT_PS_SRC_LANE1_N: Expansion-MC2 (MC2.24), DisplayPort-Source (C189.2)
DISPLAYPORT_PS_SRC_LANE1_P: Expansion-MC2 (MC2.22), DisplayPort-Source (C187.2)
GIGE_INT_B: USB_Ethernet (R107.1 U16.38), Expansion-MC1 (MC1.91)
GIGE_LED_MODE: USB_Ethernet (R108.1 R114.2 U16.41), Expansion-MC1 (MC1.94)
GIGE_MDC: USB_Ethernet (R105.1 U16.36), Expansion-MC1 (MC1.102)
GIGE_MDIO: USB_Ethernet (R106.1 U16.37), Expansion-MC1 (MC1.100)
GIGE_RESET_B: USB_Ethernet (D3.2 R117.1), Expansion-MC1 (MC1.92)
GIGE_RX_CLK: USB_Ethernet (R91.1 R99.2 U16.35), Expansion-MC1 (MC1.64)
GIGE_RX_DV: USB_Ethernet (R90.1 R98.2 U16.33), Expansion-MC1 (MC1.67)
GIGE_RXD0: USB_Ethernet (R95.1 R103.2 U16.32), Expansion-MC1 (MC1.68)
GIGE_RXD1: USB_Ethernet (R94.1 R102.2 U16.31), Expansion-MC1 (MC1.65)
GIGE_RXD2: USB_Ethernet (R93.1 R101.2 U16.28), Expansion-MC1 (MC1.69)
GIGE_RXD3: USB_Ethernet (R92.1 R100.2 U16.27), Expansion-MC1 (MC1.70)
GIGE_TX_CLK: USB_Ethernet (U16.24), Expansion-MC1 (MC1.71)
GIGE_TX_EN: USB_Ethernet (U16.25), Expansion-MC1 (MC1.66)
GIGE_TXD0: USB_Ethernet (U16.19), Expansion-MC1 (MC1.72)
GIGE_TXD1: USB_Ethernet (U16.20), Expansion-MC1 (MC1.62)
GIGE_TXD2: USB_Ethernet (U16.21), Expansion-MC1 (MC1.61)
GIGE_TXD3: USB_Ethernet (U16.22), Expansion-MC1 (MC1.63)
PS_I2C0_SCL_3V3: USB_Ethernet (U14.26 U15.6), Expansion-MC1 (J1.1 MC1.58 U1.6), Expansion-MC2 (J6.1 J7.1 U2.12), Expansion-MC3 (J8.1 J9.1 J11.1), Power (U19.43), DisplayPort-Sink-SATA (U6.7), DisplayPort-Source (U25.15)
PS_I2C0_SDA_3V3: USB_Ethernet (U14.25 U15.5), Expansion-MC1 (J1.3 MC1.60 U1.5), Expansion-MC2 (J6.3 J7.3 U2.19), Expansion-MC3 (J8.3 J9.3 J11.3), Power (U19.42), DisplayPort-Sink-SATA (U6.8), DisplayPort-Source (U25.14)
QSFP1_INT_B: QSFP (R51.1 U9.3), Expansion-MC3 (MC3.42)
QSFP1_LP_MODE: QSFP (U8.9), Expansion-MC3 (MC3.36)
QSFP1_MODPRS_B: QSFP (U8.7), Expansion-MC3 (MC3.40)
QSFP1_MODSEL_B: QSFP (U8.8), Expansion-MC3 (MC3.38)
QSFP1_RESET_B: QSFP (U8.10), Expansion-MC3 (MC3.34)
QSFP1_RX1N: QSFP (J14.18), Expansion-MC2 (MC2.47)
QSFP1_RX1P: QSFP (J14.17), Expansion-MC2 (MC2.45)
QSFP1_RX2N: QSFP (J14.21), Expansion-MC2 (MC2.43)
QSFP1_RX2P: QSFP (J14.22), Expansion-MC2 (MC2.41)
QSFP1_RX3N: QSFP (J14.15), Expansion-MC2 (MC2.39)
QSFP1_RX3P: QSFP (J14.14), Expansion-MC2 (MC2.37)
QSFP1_RX4N: QSFP (J14.24), Expansion-MC2 (MC2.35)
QSFP1_RX4P: QSFP (J14.25), Expansion-MC2 (MC2.33)
QSFP1_SCL: QSFP (R55.1 U10.2), Expansion-MC3 (MC3.44)
QSFP1_SDA: QSFP (R56.1 U10.3), Expansion-MC3 (MC3.46)
QSFP1_TX1N: QSFP (J14.37), Expansion-MC2 (MC2.48)
QSFP1_TX1P: QSFP (J14.36), Expansion-MC2 (MC2.46)
QSFP1_TX2N: QSFP (J14.2), Expansion-MC2 (MC2.44)
QSFP1_TX2P: QSFP (J14.3), Expansion-MC2 (MC2.42)
QSFP1_TX3N: QSFP (J14.34), Expansion-MC2 (MC2.40)
QSFP1_TX3P: QSFP (J14.33), Expansion-MC2 (MC2.38)
QSFP1_TX4N: QSFP (J14.5), Expansion-MC2 (MC2.36)
QSFP1_TX4P: QSFP (J14.6), Expansion-MC2 (MC2.34)
QSFP2_INT_B: QSFP (R50.1 U9.2), Expansion-MC3 (MC3.45)
QSFP2_LP_MODE: QSFP (U8.3), Expansion-MC3 (MC3.37)
QSFP2_MODPRS_B: QSFP (U8.1), Expansion-MC3 (MC3.41)
QSFP2_MODSEL_B: QSFP (U8.2), Expansion-MC3 (MC3.39)
QSFP2_RESET_B: QSFP (U8.4), Expansion-MC3 (MC3.35)
QSFP2_RX1N: QSFP (J15.18), Expansion-MC2 (MC2.63)
QSFP2_RX1P: QSFP (J15.17), Expansion-MC2 (MC2.61)
QSFP2_RX2N: QSFP (J15.21), Expansion-MC2 (MC2.59)
QSFP2_RX2P: QSFP (J15.22), Expansion-MC2 (MC2.57)
QSFP2_RX3N: QSFP (J15.15), Expansion-MC2 (MC2.55)
QSFP2_RX3P: QSFP (J15.14), Expansion-MC2 (MC2.53)
QSFP2_RX4N: QSFP (J15.24), Expansion-MC2 (MC2.51)
QSFP2_RX4P: QSFP (J15.25), Expansion-MC2 (MC2.49)
QSFP2_SCL: QSFP (R61.1 U11.2), Expansion-MC3 (MC3.47)
QSFP2_SDA: QSFP (R62.1 U11.3), Expansion-MC3 (MC3.43)
QSFP2_TX1N: QSFP (J15.37), Expansion-MC2 (MC2.64)
QSFP2_TX1P: QSFP (J15.36), Expansion-MC2 (MC2.62)
QSFP2_TX2N: QSFP (J15.2), Expansion-MC2 (MC2.60)
QSFP2_TX2P: QSFP (J15.3), Expansion-MC2 (MC2.58)
QSFP2_TX3N: QSFP (J15.34), Expansion-MC2 (MC2.56)
QSFP2_TX3P: QSFP (J15.33), Expansion-MC2 (MC2.54)
QSFP2_TX4N: QSFP (J15.5), Expansion-MC2 (MC2.52)
QSFP2_TX4P: QSFP (J15.6), Expansion-MC2 (MC2.50)
SATA_TXA+: Expansion-MC2 (MC2.18), DisplayPort-Sink-SATA (C24.2)
SATA_TXA-: Expansion-MC2 (MC2.20), DisplayPort-Sink-SATA (C25.2)
SATA_TXB+: Expansion-MC2 (MC2.19), DisplayPort-Sink-SATA (C27.2)
SATA_TXB-: Expansion-MC2 (MC2.17), DisplayPort-Sink-SATA (C26.2)
SZG_PORTE_C2P_CLKN: Expansion-MC2 (J6.36), Expansion-MC3 (MC3.150)
SZG_PORTE_C2P_CLKP: Expansion-MC2 (J6.34), Expansion-MC3 (MC3.148)
SZG_PORTE_P2C_CLKN: Expansion-MC2 (J6.35), Expansion-MC3 (MC3.145)
SZG_PORTE_P2C_CLKP: Expansion-MC2 (J6.33), Expansion-MC3 (MC3.143)
SZG_PORTE_S0: Expansion-MC2 (J6.14), Expansion-MC3 (MC3.141)
SZG_PORTE_S1: Expansion-MC2 (J6.16), Expansion-MC3 (MC3.152)
SZG_PORTE_S2: Expansion-MC2 (J6.17), Expansion-MC3 (MC3.154)
SZG_PORTE_S3: Expansion-MC2 (J6.18), Expansion-MC3 (MC3.147)
SZG_PORTE_S4: Expansion-MC2 (J6.19), Expansion-MC3 (MC3.149)
SZG_PORTE_S5: Expansion-MC2 (J6.20), Expansion-MC3 (MC3.138)
SZG_PORTE_S6: Expansion-MC2 (J6.21), Expansion-MC3 (MC3.140)
SZG_PORTE_S7: Expansion-MC2 (J6.22), Expansion-MC3 (MC3.142)
SZG_PORTE_S8: Expansion-MC2 (J6.23), Expansion-MC3 (MC3.144)
SZG_PORTE_S9: Expansion-MC2 (J6.24), Expansion-MC3 (MC3.146)
SZG_PORTF_C2P_CLKN: Expansion-MC1 (MC1.46), Expansion-MC2 (J7.36)
SZG_PORTF_C2P_CLKP: Expansion-MC1 (MC1.44), Expansion-MC2 (J7.34)
SZG_PORTF_P2C_CLKN: Expansion-MC1 (MC1.36), Expansion-MC2 (J7.35)
SZG_PORTF_P2C_CLKP: Expansion-MC1 (MC1.34), Expansion-MC2 (J7.33)
SZG_PORTF_S0: Expansion-MC1 (MC1.35), Expansion-MC2 (J7.14)
SZG_PORTF_S1: Expansion-MC1 (MC1.37), Expansion-MC2 (J7.16)
SZG_PORTF_S2: Expansion-MC1 (MC1.39), Expansion-MC2 (J7.17)
SZG_PORTF_S3: Expansion-MC1 (MC1.41), Expansion-MC2 (J7.18)
SZG_PORTF_S4: Expansion-MC1 (MC1.43), Expansion-MC2 (J7.19)
SZG_PORTF_S5: Expansion-MC1 (MC1.45), Expansion-MC2 (J7.20)
SZG_PORTF_S6: Expansion-MC1 (MC1.47), Expansion-MC2 (J7.21)
SZG_PORTF_S7: Expansion-MC1 (MC1.38), Expansion-MC2 (J7.22)
SZG_PORTF_S8: Expansion-MC1 (MC1.40), Expansion-MC2 (J7.23)
SZG_PORTF_S9: Expansion-MC1 (MC1.42), Expansion-MC2 (J7.24)
USB_CLKOUT: USB_Ethernet (U13.1), Expansion-MC1 (MC1.93)
USB_DATA0: USB_Ethernet (U13.3), Expansion-MC1 (MC1.105)
USB_DATA1: USB_Ethernet (U13.4), Expansion-MC1 (MC1.108)
USB_DATA2: USB_Ethernet (U13.5), Expansion-MC1 (MC1.97)
USB_DATA3: USB_Ethernet (U13.6), Expansion-MC1 (MC1.103)
USB_DATA4: USB_Ethernet (U13.7), Expansion-MC1 (MC1.101)
USB_DATA5: USB_Ethernet (U13.9), Expansion-MC1 (MC1.104)
USB_DATA6: USB_Ethernet (U13.10), Expansion-MC1 (MC1.98)
USB_DATA7: USB_Ethernet (U13.13), Expansion-MC1 (MC1.106)
USB_DIR: USB_Ethernet (U13.31), Expansion-MC1 (MC1.95)
USB_NXT: USB_Ethernet (U13.2), Expansion-MC1 (MC1.107)
USB_RESET_B: USB_Ethernet (U13.27), Expansion-MC1 (MC1.96)
USB_SSRX_N: USB_Ethernet (U14.10), Expansion-MC2 (MC2.15)
USB_SSRX_P: USB_Ethernet (U14.9), Expansion-MC2 (MC2.13)
USB_SSTX_N: USB_Ethernet (U14.7), Expansion-MC2 (MC2.16)
USB_SSTX_P: USB_Ethernet (U14.6), Expansion-MC2 (MC2.14)
USB_STP: USB_Ethernet (U13.29), Expansion-MC1 (MC1.99)
USB_TYPEC_INT_B: USB_Ethernet (R80.1 U14.23), Expansion-MC1 (MC1.74)

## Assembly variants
DEFAULT: not fitted C28 C29 C30 C31 C32 C33 C34 C35 C36 C37 C38 C39 C40 C41 C42 C43 C44 C45 C46 C47 C48 C112 C154 C160 C165 C166 C169 C170 C171 C172 C173 C176 C177 C182 C183 C185 C187 C189 C190 C191 C192 C193 C194 C195 C196 C197 C198 C199 C200 C201 C202 C203 C204 C205 C206 C207 C208 C209 C210 C211 D2 D3 J13 J20 J21 R2 R3 R7 R9 R10 R11 R19 R20 R21 R22 R23 R24 R25 R26 R27 R28 R29 R30 R31 R32 R33 R34 R35 R36 R37 R38 R39 R40 R47 R60 R70 R73 R83 R87 R88 R89 R90 R91 R100 R101 R102 R103 R108 R110 R111 R113 R119 R121 R141 R144 R145 R146 R147 R153 R154 R155 R156 R157 R158 R159 R160 R161 R162 R163 R164 R165 R166 R167 R168 R169 R170 R171 R172 R173 R174 R175 R176 R177 R178 R179 R180 R181 R182 U6 U7 U22 U24 U25 U26 Y2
